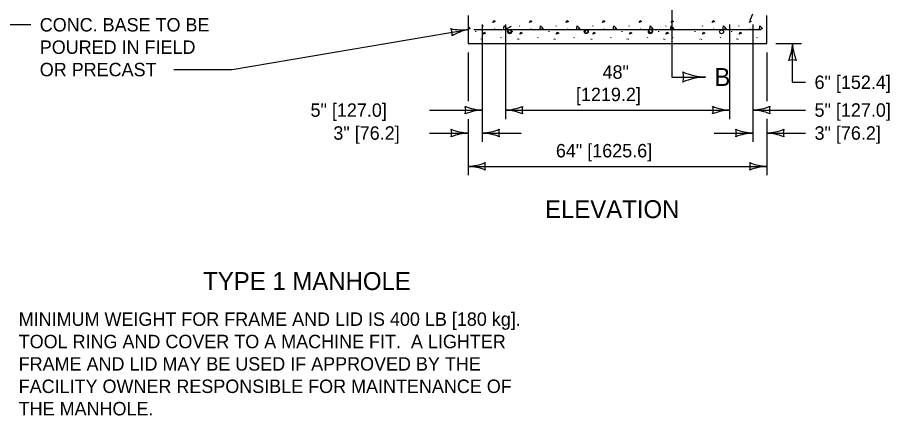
# Model space of a CAD drawing. Extents: x 49991.4 to 50028.3, y 49987.6 to 50011.4.
# Drawn here: x 50005.208 to 50009.103, y 49993.501 to 49995.28 of the extents above; entities that cross this region are included whole.
import ezdxf

# ---------------------------------------------------------------- set-up
doc = ezdxf.new("R2010")
doc.units = 0
for name, color, linetype in [('Level 1', 7, 'Continuous'), ('Level 2', 7, 'Continuous'), ('Level 3', 7, 'Continuous'), ('Level 6', 7, 'Continuous')]:
    doc.layers.add(name, color=color, linetype=linetype)

msp = doc.modelspace()

# ---------------------------------------------------------------- linework, layer by layer
at = {"layer": 'Level 1'}
for p, q in [((50007.221, 49995.2888), (50007.221, 49995.1638)), ((50008.5543, 49995.1638), (50008.5543, 49995.2888)), ((50007.246, 49995.2263), (50008.5293, 49995.2263)), ((50007.2538, 49995.2189), (50007.2541, 49995.2159)), ((50007.2872, 49995.2409), (50007.2886, 49995.2439)), ((50007.3378, 49995.2272), (50007.3392, 49995.2302)), ((50007.417, 49995.2189), (50007.4174, 49995.2159)), ((50007.4505, 49995.2409), (50007.4518, 49995.2439)), ((50007.5011, 49995.2272), (50007.5024, 49995.2302)), ((50007.5803, 49995.2189), (50007.5806, 49995.2159)), ((50007.6138, 49995.2409), (50007.6151, 49995.2439)), ((50007.6644, 49995.2272), (50007.6657, 49995.2302)), ((50007.7436, 49995.2189), (50007.7439, 49995.2159)), ((50007.777, 49995.2409), (50007.7784, 49995.2439)), ((50007.8276, 49995.2272), (50007.829, 49995.2302)), ((50007.9068, 49995.2189), (50007.9072, 49995.2159)), ((50007.9403, 49995.2409), (50007.9416, 49995.2439)), ((50007.9909, 49995.2272), (50007.9922, 49995.2302)), ((50008.0701, 49995.2189), (50008.0704, 49995.2159)), ((50008.1036, 49995.2409), (50008.1049, 49995.2439)), ((50008.134, 49995.2272), (50008.1353, 49995.2302)), ((50008.2333, 49995.2189), (50008.2337, 49995.2159)), ((50008.2668, 49995.2409), (50008.2682, 49995.2439)), ((50008.3174, 49995.2272), (50008.3188, 49995.2302)), ((50008.3966, 49995.2189), (50008.3969, 49995.2159)), ((50008.4301, 49995.2409), (50008.4314, 49995.2439)), ((50008.4807, 49995.2272), (50008.482, 49995.2302)), ((50007.2765, 49995.1847), (50007.2778, 49995.1827)), ((50007.2816, 49995.184), (50007.2829, 49995.182)), ((50007.3682, 49995.1886), (50007.3695, 49995.1916)), ((50007.4397, 49995.1847), (50007.4411, 49995.1827)), ((50007.4448, 49995.184), (50007.4462, 49995.182)), ((50007.5314, 49995.1886), (50007.5327, 49995.1916)), ((50007.603, 49995.1847), (50007.6043, 49995.1827)), ((50007.6081, 49995.184), (50007.6094, 49995.182)), ((50007.6947, 49995.1886), (50007.696, 49995.1916)), ((50007.7663, 49995.1847), (50007.7676, 49995.1827)), ((50007.7714, 49995.184), (50007.7727, 49995.182)), ((50007.8579, 49995.1886), (50007.8593, 49995.1916)), ((50007.9295, 49995.1847), (50007.9309, 49995.1827)), ((50007.9346, 49995.184), (50007.936, 49995.182)), ((50008.0212, 49995.1886), (50008.0225, 49995.1916)), ((50008.0928, 49995.1847), (50008.0941, 49995.1827)), ((50008.0979, 49995.184), (50008.0992, 49995.182)), ((50008.1345, 49995.1886), (50008.1358, 49995.1916)), ((50008.2561, 49995.1847), (50008.2574, 49995.1827)), ((50008.2612, 49995.184), (50008.2625, 49995.182)), ((50008.3477, 49995.1886), (50008.3491, 49995.1916)), ((50008.4193, 49995.1847), (50008.4206, 49995.1827)), ((50008.4244, 49995.184), (50008.4258, 49995.182)), ((50008.511, 49995.1886), (50008.5123, 49995.1916)), ((50007.221, 49995.1638), (50008.5543, 49995.1638))]:
    msp.add_line(p, q, dxfattribs=at)
for points in [[(50008.4913, 49995.2941), (50008.4781, 49995.2664), (50008.4848, 49995.2614), (50008.4741, 49995.258)], [(50007.3312, 49995.258), (50007.3352, 49995.2664), (50007.3419, 49995.2614), (50007.3312, 49995.258)], [(50007.4945, 49995.258), (50007.4985, 49995.2664), (50007.5052, 49995.2614), (50007.4945, 49995.258)], [(50007.6578, 49995.258), (50007.6618, 49995.2664), (50007.6684, 49995.2614), (50007.6578, 49995.258)], [(50007.821, 49995.258), (50007.825, 49995.2664), (50007.8317, 49995.2614), (50007.821, 49995.258)], [(50007.9843, 49995.258), (50007.9883, 49995.2664), (50007.995, 49995.2614), (50007.9843, 49995.258)], [(50008.1274, 49995.258), (50008.1314, 49995.2664), (50008.138, 49995.2614), (50008.1274, 49995.258)], [(50008.3108, 49995.258), (50008.3148, 49995.2664), (50008.3215, 49995.2614), (50008.3108, 49995.258)], [(50007.221, 49995.2394), (50007.2296, 49995.2305), (50007.221, 49995.2265)], [(50007.2879, 49995.2059), (50007.2919, 49995.2142), (50007.2986, 49995.2092), (50007.2879, 49995.2059)], [(50007.3784, 49995.2238), (50007.381, 49995.2428), (50007.3929, 49995.2305), (50007.4149, 49995.2407)], [(50007.4512, 49995.2059), (50007.4552, 49995.2142), (50007.4618, 49995.2092), (50007.4512, 49995.2059)], [(50007.5416, 49995.2238), (50007.5442, 49995.2428), (50007.5562, 49995.2305), (50007.5419, 49995.2239)], [(50007.6144, 49995.2059), (50007.6184, 49995.2142), (50007.6251, 49995.2092), (50007.6144, 49995.2059)], [(50007.7049, 49995.2238), (50007.7075, 49995.2428), (50007.7194, 49995.2305), (50007.7052, 49995.2239)], [(50007.7777, 49995.2059), (50007.7817, 49995.2142), (50007.7883, 49995.2092), (50007.7777, 49995.2059)], [(50007.8682, 49995.2238), (50007.8708, 49995.2428), (50007.8827, 49995.2305), (50007.8684, 49995.2239)], [(50007.941, 49995.2059), (50007.945, 49995.2142), (50007.9516, 49995.2092), (50007.941, 49995.2059)], [(50008.0314, 49995.2238), (50008.034, 49995.2428), (50008.046, 49995.2305), (50008.0317, 49995.2239)], [(50008.1042, 49995.2059), (50008.1082, 49995.2142), (50008.1149, 49995.2092), (50008.1042, 49995.2059)], [(50008.1245, 49995.2238), (50008.1271, 49995.2428), (50008.139, 49995.2305), (50008.1248, 49995.2239)], [(50008.2675, 49995.2059), (50008.2715, 49995.2142), (50008.2781, 49995.2092), (50008.2675, 49995.2059)], [(50008.358, 49995.2238), (50008.3606, 49995.2428), (50008.3725, 49995.2305), (50008.3582, 49995.2239)], [(50008.4308, 49995.2059), (50008.4348, 49995.2142), (50008.4414, 49995.2092), (50008.4308, 49995.2059)], [(50008.5212, 49995.2238), (50008.5238, 49995.2428), (50008.5358, 49995.2305), (50008.5215, 49995.2239)]]:
    msp.add_lwpolyline(points, dxfattribs=at)
for centre, radius in [((50007.4057, 49995.2159), 0.00893), ((50007.4057, 49995.2187), 0.0074), ((50007.7478, 49995.2166), 0.00893), ((50007.7478, 49995.2166), 0.0074), ((50008.0343, 49995.2167), 0.00893), ((50008.0353, 49995.2187), 0.0074), ((50008.3522, 49995.2157), 0.00893)]:
    msp.add_circle(centre, radius, dxfattribs=at)
at = {"layer": 'Level 3'}
for p, q in [((50005.2672, 49995.2471), (50005.0938, 49995.2471)), ((50006.1659, 49995.0471), (50007.221, 49995.2263)), ((50007.2835, 49995.2488), (50007.2835, 49994.7235)), ((50007.3877, 49995.2488), (50007.3877, 49994.8259)), ((50008.3883, 49995.2488), (50008.3883, 49994.8259)), ((50008.4924, 49995.2488), (50008.4924, 49994.7235)), ((50008.5943, 49995.1638), (50008.7093, 49995.1638)), ((50008.6693, 49994.9904), (50008.6693, 49995.1638)), ((50007.221, 49995.1238), (50007.221, 49994.9059)), ((50008.5543, 49995.1238), (50008.5543, 49994.9062)), ((50005.9057, 49995.0471), (50006.1659, 49995.0471)), ((50008.6693, 49994.9904), (50008.7277, 49994.9904)), ((50007.0476, 49994.8659), (50007.2835, 49994.8659)), ((50007.3877, 49994.8659), (50008.3883, 49994.8659)), ((50008.4924, 49994.8662), (50008.7277, 49994.8662)), ((50007.221, 49994.8259), (50007.221, 49994.5746)), ((50008.5543, 49994.8262), (50008.5543, 49994.5746)), ((50007.0476, 49994.7635), (50007.221, 49994.7635)), ((50007.2835, 49994.7635), (50007.4569, 49994.7635)), ((50008.319, 49994.7635), (50008.4924, 49994.7635)), ((50008.5543, 49994.7635), (50008.7277, 49994.7635)), ((50007.221, 49994.6146), (50008.5543, 49994.6146))]:
    msp.add_line(p, q, dxfattribs=at)
for centre, radius, start, end in [((50007.1928, 49995.4469), 0.2223, 257.0955, 277.279), ((50007.0946, 49995.2049), 0.0548, 351.7783, 27.5007), ((50007.2713, 49994.9988), 0.233, 102.4668, 121.7167), ((50008.4472, 49995.173), 0.2223, 337.456, 357.6395), ((50008.902, 49995.1753), 0.233, 182.8273, 202.0772), ((50008.6693, 49995.0356), 0.0548, 72.1388, 107.8612), ((50008.2928, 49995.31), 0.2964, 247.456, 267.6395), ((50008.1097, 49995.0138), 0.073, 342.1388, 17.8612), ((50008.2959, 49994.7035), 0.3107, 92.8273, 112.0772), ((50007.2927, 49995.0881), 0.2223, 247.456, 267.6395), ((50007.1553, 49994.8659), 0.0548, 342.1388, 17.8612), ((50007.295, 49994.6332), 0.233, 92.8273, 112.0772), ((50007.3762, 49995.0986), 0.233, 272.8273, 292.0772), ((50007.3786, 49994.6438), 0.2223, 67.456, 87.6395), ((50007.5159, 49994.8659), 0.0548, 162.1388, 197.8612), ((50008.3975, 49995.0881), 0.2223, 247.456, 267.6395), ((50008.2601, 49994.8659), 0.0548, 342.1388, 17.8612), ((50008.3998, 49994.6332), 0.233, 92.8273, 112.0772), ((50008.4809, 49995.0989), 0.233, 272.8273, 292.0772), ((50008.4833, 49994.6441), 0.2223, 67.456, 87.6395), ((50008.6206, 49994.8662), 0.0548, 162.1388, 197.8612), ((50007.2302, 49994.9857), 0.2223, 247.456, 267.6395), ((50007.0928, 49994.7635), 0.0548, 342.1388, 17.8612), ((50007.2325, 49994.5308), 0.233, 92.8273, 112.0772), ((50007.272, 49994.9962), 0.233, 272.8273, 292.0772), ((50007.2744, 49994.5414), 0.2223, 67.456, 87.6395), ((50007.4117, 49994.7635), 0.0548, 162.1388, 197.8612), ((50008.3642, 49994.7635), 0.0548, 342.1388, 17.8612), ((50008.5039, 49994.9962), 0.233, 247.9228, 267.1727), ((50008.5016, 49994.5414), 0.2223, 92.3605, 112.544), ((50008.5452, 49994.9857), 0.2223, 272.3605, 292.544), ((50008.5428, 49994.5308), 0.233, 67.9228, 87.1727), ((50008.6825, 49994.7635), 0.0548, 162.1388, 197.8612), ((50007.2095, 49994.8473), 0.233, 272.8273, 292.0772), ((50007.3492, 49994.6146), 0.0548, 162.1388, 197.8612), ((50008.5635, 49994.8367), 0.2223, 247.456, 267.6395), ((50008.4261, 49994.6146), 0.0548, 342.1388, 17.8612), ((50007.2119, 49994.3925), 0.2223, 67.456, 87.6395), ((50008.5658, 49994.3819), 0.233, 92.8273, 112.0772)]:
    msp.add_arc(centre, radius, start, end, dxfattribs=at)
at = {"layer": 'Level 6'}
for p, q in [((50008.1306, 49995.5334), (50008.1306, 49995.0138)), ((50008.1306, 49995.0138), (50008.2806, 49995.0138))]:
    msp.add_line(p, q, dxfattribs=at)

# ---------------------------------------------------------------- texts
at = {"layer": 'Level 2'}
for s, height, p in [('CONC. BASE TO BE', 0.06, (50005.3072, 49995.2171)), ('POURED IN FIELD', 0.06, (50005.3072, 49995.1171)), ('OR PRECAST', 0.06, (50005.3072, 49995.0171)), ('48"', 0.06, (50007.8208, 49995.0059)), ('B', 0.0799, (50008.3206, 49994.9739)), ('6" [152.4]', 0.06, (50008.7677, 49994.9604)), ('[1219.2]', 0.06, (50007.7021, 49994.9059)), ('5" [127.0]', 0.06, (50006.5166, 49994.8359)), ('5" [127.0]', 0.06, (50008.7677, 49994.8362)), ('3" [76.2]', 0.06, (50006.6185, 49994.7335)), ('3" [76.2]', 0.06, (50008.7677, 49994.7335)), ('64" [1625.6]', 0.06, (50007.6125, 49994.6546)), ('ELEVATION', 0.08, (50007.5638, 49994.3833)), ('TYPE 1 MANHOLE', 0.08, (50006.0372, 49994.062)), ('MINIMUM WEIGHT FOR FRAME AND LID IS 400 LB [180 kg].', 0.06, (50005.2131, 49993.902)), ('TOOL RING AND COVER TO A MACHINE FIT.  A LIGHTER', 0.06, (50005.2131, 49993.802)), ('FRAME AND LID MAY BE USED IF APPROVED BY THE', 0.06, (50005.2131, 49993.702)), ('FACILITY OWNER RESPONSIBLE FOR MAINTENANCE OF', 0.06, (50005.2131, 49993.602)), ('THE MANHOLE.', 0.06, (50005.2131, 49993.502))]:
    msp.add_text(s, height=height, dxfattribs=at).set_placement(p)

doc.saveas('drawing.dxf')
